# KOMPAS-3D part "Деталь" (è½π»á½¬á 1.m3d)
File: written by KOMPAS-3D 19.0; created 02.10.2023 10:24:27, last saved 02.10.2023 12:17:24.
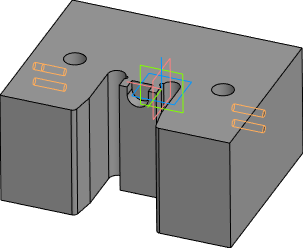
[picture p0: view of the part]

Document properties: Автор: admin; Организация: Hewlett-Packard Company; Полное имя файла: C:\Users\Petrenko-VE\Documents\Клупалка_1.m3d

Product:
- Part/product: Деталь
    Масса: 51.7411
  - Body: Тело 1
      Масса: 12.1633

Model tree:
1. Эскиз:1
2. Элемент выдавливания:1
     Расстояние 1 = 40
3. Эскиз:2  (with: Элемент выдавливания:1)
4. Элемент выдавливания:2
     Расстояние 2 = 40
5. Эскиз:4  (with: Элемент выдавливания:1, Элемент выдавливания:2)
6. Элемент выдавливания:3
     Расстояние 2 = 6.25
7. Эскиз:5  (with: Элемент выдавливания:3)
8. Элемент выдавливания:4
     Расстояние 2 = 14
9. Эскиз:6  (with: Элемент выдавливания:1, Элемент выдавливания:2)
10. Элемент выдавливания:5
11. Эскиз:7  (with: Элемент выдавливания:1, Элемент выдавливания:2)
12. Элемент выдавливания:6
     Расстояние 1 = 60
13. Элемент выдавливания:7  (with: Элемент выдавливания:1)
     Расстояние 1 = 60
14. Фаска:1  (with: Элемент выдавливания:6)
     Угол = 80.5377; Длина 1 = 5; Длина 2 = 30
15. Фаска:2  (with: Элемент выдавливания:7)
     Угол = 80.5377; Длина 1 = 5; Длина 2 = 30
16. Скругление:1  (with: Фаска:2, Фаска:1)
     Радиус = 5
17. Элемент выдавливания:8  (with: Элемент выдавливания:1)
     Расстояние 1 = 95
18. Эскиз:8  (with: Элемент выдавливания:1, Элемент выдавливания:2)
19. Элемент выдавливания:9
20. Эскиз:9  (with: Элемент выдавливания:1, Элемент выдавливания:7)
21. Элемент выдавливания:10
     Расстояние 2 = 50
22. Эскиз:10  (with: Элемент выдавливания:1, Элемент выдавливания:6)
23. Элемент выдавливания:11
     Расстояние 2 = 50
24. Условное изображение резьбы:1  (with: Элемент выдавливания:11)  (labels: M8; cil0_24705-2004 coarse)
     Длина резьбы = 10; Шаг резьбы = 1.25; Номинальный диаметр резьбы = 8
25. Подгонка:1  (with: Элемент выдавливания:11)
26. Условное изображение резьбы:2  (with: Элемент выдавливания:11)  (labels: M8; cil0_24705-2004 coarse)
     Длина резьбы = 36.1573; Шаг резьбы = 1.25; Номинальный диаметр резьбы = 8
27. Подгонка:2  (with: Элемент выдавливания:11)
28. Условное изображение резьбы:3  (with: Элемент выдавливания:11)  (labels: M8; cil0_24705-2004 coarse)
     Длина резьбы = 36.1573; Шаг резьбы = 1.25; Номинальный диаметр резьбы = 8
29. Подгонка:3  (with: Элемент выдавливания:11)
30. Условное изображение резьбы:4  (with: Элемент выдавливания:10)  (labels: M8; cil0_24705-2004 coarse)
     Длина резьбы = 36.1573; Шаг резьбы = 1.25; Номинальный диаметр резьбы = 8
31. Подгонка:4  (with: Элемент выдавливания:10)
32. Условное изображение резьбы:5  (with: Элемент выдавливания:10)  (labels: M8; cil0_24705-2004 coarse)
     Длина резьбы = 36.1573; Шаг резьбы = 1.25; Номинальный диаметр резьбы = 8
33. Подгонка:5  (with: Элемент выдавливания:10)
